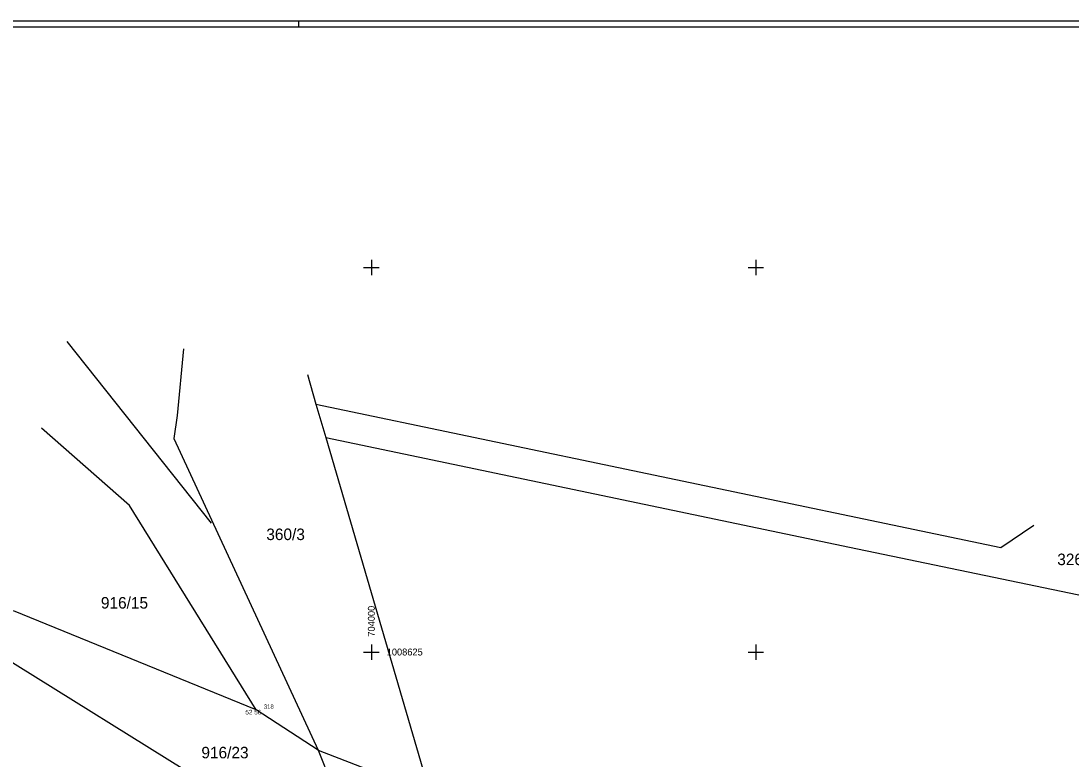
# Model space of a CAD drawing. Extents: x -704057 to -703795, y -1008732 to -1008584.
# Drawn here: x -704022.8 to -703954.5, y -1008632 to -1008584 of the extents above; entities that cross this region are included whole.
import ezdxf

# ---------------------------------------------------------------- set-up
doc = ezdxf.new("R2010")
doc.units = 0
for name, color, linetype in [('Z_body', 7, 'Continuous'), ('Z_body_cisla', 7, 'Continuous'), ('Z_body_vysky', 7, 'Continuous'), ('Z_hekt_sit', 7, 'Continuous'), ('Z_hekt_sit_popis', 7, 'Continuous'), ('Z_katastr_cisla_pozemkove', 7, 'Continuous'), ('Z_katastr_hranice', 7, 'Continuous'), ('Z_katastr_hranice_KU', 7, 'Continuous'), ('Z_katastr_vnitrni_kresba', 7, 'Continuous'), ('Z_plotbox', 7, 'Continuous'), ('Z_ramecek_tisk', 7, 'Continuous')]:
    doc.layers.add(name, color=color, linetype=linetype)

# ---------------------------------------------------------------- blocks, each defined once
blk = doc.blocks.new('POINT_DISPLAY')
blk.add_line((0, 0), (0, 0))

msp = doc.modelspace()

# ---------------------------------------------------------------- linework, layer by layer
at = {"layer": 'Z_hekt_sit'}
for p, q in [((-704000, -1008599.5), (-704000, -1008600.5)), ((-703975, -1008599.5), (-703975, -1008600.5)), ((-704000.5, -1008600), (-703999.5, -1008600)), ((-703975.5, -1008600), (-703974.5, -1008600)), ((-704000.5, -1008625), (-703999.5, -1008625)), ((-704000, -1008624.5), (-704000, -1008625.5)), ((-703975.5, -1008625), (-703974.5, -1008625)), ((-703975, -1008624.5), (-703975, -1008625.5))]:
    msp.add_line(p, q, dxfattribs=at)
at = {"layer": 'Z_katastr_hranice'}
for p, q in [((-704010.4, -1008616.61), (-704019.77, -1008604.8)), ((-704004.16, -1008606.95), (-704003.6, -1008608.87)), ((-704003.6, -1008608.87), (-703982.06, -1008613.38)), ((-704003.6, -1008608.87), (-704002.96, -1008611.05)), ((-704015.73, -1008615.46), (-704021.45, -1008610.44)), ((-704002.96, -1008611.05), (-703968.91, -1008618.17)), ((-704002.96, -1008611.05), (-703996.18, -1008634.19)), ((-703982.06, -1008613.38), (-703959.06, -1008618.2)), ((-704007.49, -1008628.76), (-704015.73, -1008615.46)), ((-703959.06, -1008618.2), (-703956.93, -1008616.75)), ((-703968.91, -1008618.17), (-703949.24, -1008622.28)), ((-704007.49, -1008628.76), (-704023.27, -1008622.32)), ((-703999.92, -1008640.28), (-704025.1, -1008624.6)), ((-704003.46, -1008631.38), (-704007.49, -1008628.76))]:
    msp.add_line(p, q, dxfattribs=at)
at = {"layer": 'Z_katastr_hranice_KU'}
for p, q in [((-704012.21, -1008605.28), (-704012.62, -1008609.62)), ((-704012.62, -1008609.62), (-704012.85, -1008611.12)), ((-704012.85, -1008611.12), (-704003.46, -1008631.38)), ((-704003.46, -1008631.38), (-703999.92, -1008640.28))]:
    msp.add_line(p, q, dxfattribs=at)
at = {"layer": 'Z_katastr_vnitrni_kresba'}
msp.add_line((-704003.46, -1008631.38), (-703996.18, -1008634.19), dxfattribs=at)
at = {"layer": 'Z_plotbox'}
for p, q in [((-704057.23, -1008583.96), (-703794.73, -1008583.96)), ((-704004.73, -1008583.96), (-704004.73, -1008584.34))]:
    msp.add_line(p, q, dxfattribs=at)
at = {"layer": 'Z_ramecek_tisk'}
msp.add_line((-704056.86, -1008584.34), (-703795.11, -1008584.34), dxfattribs=at)

# ---------------------------------------------------------------- block references
at = {"layer": 'Z_body'}
msp.add_blockref('POINT_DISPLAY', (-704007.49, -1008628.76), dxfattribs=at)

# ---------------------------------------------------------------- texts
at = {"layer": 'Z_body_cisla'}
msp.add_text('318', height=0.28, dxfattribs=at).set_placement((-704006.99, -1008628.69))
at = {"layer": 'Z_body_vysky'}
msp.add_text('52 56', height=0.3, dxfattribs=at).set_placement((-704008.19, -1008629.06))
at = {"layer": 'Z_hekt_sit_popis'}
msp.add_text('704000', height=0.45, rotation=90, dxfattribs=at).set_placement((-703999.775, -1008624))
msp.add_text('1008625', height=0.45, dxfattribs=at).set_placement((-703999, -1008625.225))
at = {"layer": 'Z_katastr_cisla_pozemkove'}
for s, p in [('360/3', (-704006.83, -1008617.72)), ('326/11', (-703955.4, -1008619.35)), ('916/15', (-704017.585, -1008622.175)), ('916/23', (-704011.05, -1008631.915))]:
    msp.add_text(s, height=0.75, dxfattribs=at).set_placement(p)

doc.saveas('drawing.dxf')
